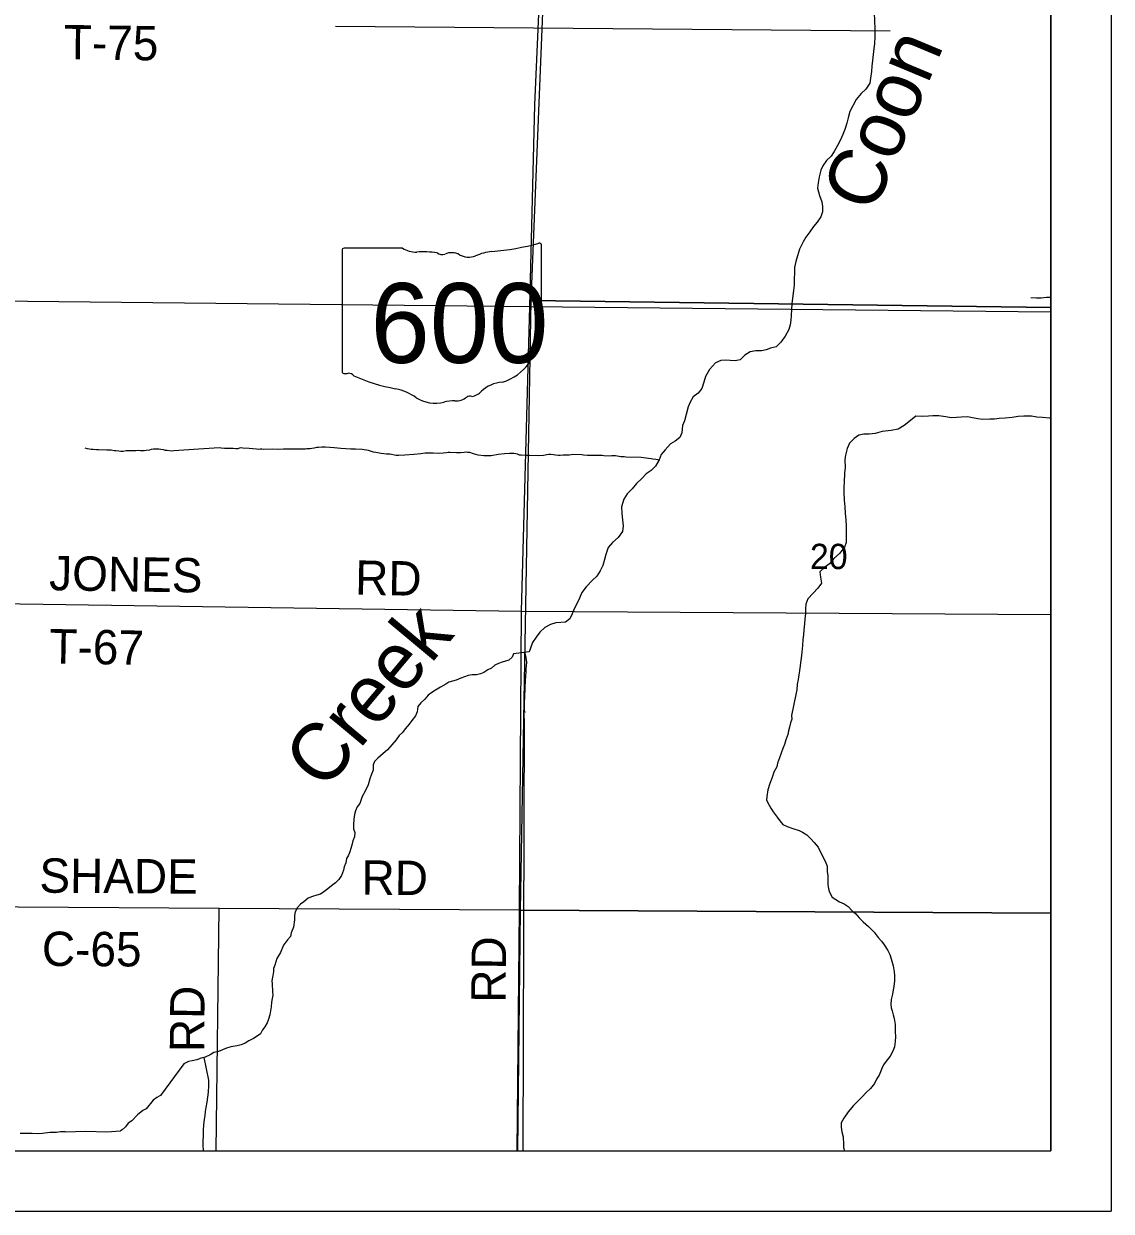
# Model space of a CAD drawing. Extents: x 0 to 34, y 0 to 22.
# Drawn here: x 7.202 to 9, y 14 to 15.963 of the extents above; entities that cross this region are included whole.
import ezdxf

# ---------------------------------------------------------------- set-up
doc = ezdxf.new("R2010")
doc.units = 0
for name, color, linetype in [('Default', 7, 'Continuous'), ('GM_X_County_Road', 7, 'Continuous'), ('GM_X_County_Road_Text', 7, 'Continuous'), ('GM_X_Minor_River', 7, 'Continuous'), ('GM_X_Minor_River_Text', 7, 'Continuous'), ('GM_X_Section_Text', 7, 'Continuous'), ('GM_X_State_Location', 7, 'Continuous'), ('GM_X_State_Route', 7, 'Continuous'), ('GM_X_State_Shield', 7, 'Continuous'), ('GM_X_Township_Road', 7, 'Continuous'), ('GM_X_Township_Road_Text', 7, 'Continuous'), ('SH_Cut_Line', 7, 'Continuous'), ('SH_Data', 7, 'Continuous')]:
    doc.layers.add(name, color=color, linetype=linetype)

msp = doc.modelspace()

# ---------------------------------------------------------------- linework, layer by layer
at = {"layer": 'Default'}
msp.add_lwpolyline([(7.0155, 14.1), (8.9, 14.1), (8.9, 16.9874)], dxfattribs=at)
for points in [[(8.9, 15.4939), (8.9, 16.4924), (8.0805, 16.4987), (8.0402, 15.5054)], [(8.9, 14.4928), (8.9, 15.4939), (8.0402, 15.5054), (8.0226, 14.4979)], [(8.0182, 14.1), (8.9, 14.1), (8.9, 14.4928), (8.0226, 14.4979)]]:
    msp.add_lwpolyline(points, close=True, dxfattribs=at)
at = {"layer": 'GM_X_County_Road'}
msp.add_lwpolyline([(7.0265, 14.5045), (7.5252, 14.501), (8.0219, 14.4983), (8.9, 14.4934)], dxfattribs=at)
at = {"layer": 'GM_X_Minor_River'}
for p, q in [((8.6345, 15.9505), (7.7173, 15.9583)), ((8.0293, 14.8347), (8.0293, 14.8351)), ((8.0295, 14.8146), (8.0271, 14.1))]:
    msp.add_line(p, q, dxfattribs=at)
for points in [[(8.6079, 15.9807), (8.6091, 15.9545), (8.6091, 15.9416), (8.6084, 15.9294), (8.6077, 15.9218)], [(8.6077, 15.9218), (8.6066, 15.9123), (8.6051, 15.9021), (8.6044, 15.8926), (8.6037, 15.8842), (8.6022, 15.8728), (8.6007, 15.8645), (8.5943, 15.855), (8.5864, 15.8477), (8.5784, 15.8374), (8.5679, 15.8176), (8.5653, 15.8073), (8.5626, 15.7986), (8.5593, 15.7883), (8.5563, 15.78), (8.5521, 15.7701), (8.5476, 15.7617), (8.5419, 15.7518), (8.537, 15.7442), (8.5295, 15.7369), (8.5234, 15.7282), (8.5201, 15.7206), (8.5174, 15.7099), (8.5156, 15.6997), (8.5145, 15.6909), (8.5176, 15.6788), (8.5214, 15.6686), (8.5229, 15.661), (8.5226, 15.6519), (8.52, 15.6435), (8.5139, 15.6351), (8.5079, 15.6275), (8.5015, 15.6191), (8.4951, 15.6103), (8.4905, 15.6023), (8.4845, 15.5902), (8.4815, 15.5795), (8.4785, 15.5696), (8.4763, 15.5601), (8.4763, 15.5503), (8.476, 15.5423), (8.4756, 15.5305), (8.4745, 15.5218), (8.4734, 15.5138), (8.472, 15.5001), (8.4712, 15.4906), (8.4709, 15.4808), (8.4705, 15.4728), (8.469, 15.4652), (8.4668, 15.4576), (8.4612, 15.4465), (8.4536, 15.4366), (8.446, 15.429), (8.4369, 15.4267), (8.4294, 15.4236), (8.4218, 15.422), (8.4123, 15.422), (8.4032, 15.4204), (8.3945, 15.4151), (8.3866, 15.4074), (8.3782, 15.4059), (8.3702, 15.4062), (8.3623, 15.4069), (8.3547, 15.4061), (8.346, 15.4023), (8.3361, 15.3916), (8.329, 15.3798), (8.3264, 15.3703), (8.3234, 15.36), (8.3173, 15.352), (8.309, 15.3463), (8.3041, 15.3371), (8.3007, 15.3295), (8.2973, 15.317), (8.2944, 15.3067), (8.2913, 15.2987), (8.2899, 15.2866), (8.2869, 15.279), (8.2793, 15.2728), (8.2714, 15.2682), (8.2627, 15.2587), (8.2562, 15.2507), (8.2529, 15.2423), (8.2468, 15.2313), (8.2393, 15.2244), (8.2309, 15.2191), (8.2238, 15.2111), (8.2151, 15.203), (8.2079, 15.1943), (8.2, 15.1859), (8.1943, 15.1771), (8.1905, 15.1642), (8.191, 15.1532), (8.1921, 15.1426), (8.1929, 15.1327), (8.1918, 15.1236), (8.1851, 15.1137), (8.1756, 15.1056), (8.1684, 15.0969), (8.1643, 15.0855), (8.162, 15.0775)], [(8.9, 15.5101), (8.8931, 15.5103), (8.8844, 15.5095), (8.8764, 15.5095), (8.8673, 15.5098)], [(8.9, 15.311), (8.898, 15.311), (8.8866, 15.3121), (8.8771, 15.3128), (8.868, 15.3143), (8.8555, 15.3142), (8.846, 15.3138), (8.8362, 15.3122), (8.8248, 15.3107), (8.8146, 15.3102), (8.807, 15.3094), (8.799, 15.309), (8.7876, 15.3089), (8.7793, 15.31), (8.7705, 15.3115), (8.7622, 15.313), (8.7519, 15.3125), (8.744, 15.3121), (8.7352, 15.3117), (8.7265, 15.3132), (8.7151, 15.3146), (8.7053, 15.315), (8.6977, 15.3142), (8.6886, 15.3134), (8.6772, 15.314), (8.6681, 15.3068), (8.6579, 15.2988), (8.648, 15.2926), (8.6363, 15.2907), (8.6211, 15.2887), (8.6097, 15.2856), (8.5999, 15.2844), (8.5912, 15.2844), (8.5828, 15.2828), (8.5749, 15.2771), (8.5673, 15.2698), (8.5632, 15.2607), (8.5606, 15.25), (8.5598, 15.2421), (8.5599, 15.2295), (8.5592, 15.22), (8.5585, 15.2052), (8.5581, 15.1973), (8.5581, 15.1881), (8.5586, 15.1752), (8.5597, 15.1646), (8.5602, 15.154), (8.561, 15.1422), (8.5618, 15.1327), (8.5619, 15.1054), (8.5589, 15.0978), (8.5509, 15.0871), (8.5415, 15.0787), (8.5343, 15.0703), (8.5264, 15.0646), (8.5184, 15.057), (8.5192, 15.0479), (8.5208, 15.0384), (8.5151, 15.03), (8.5072, 15.0216), (8.4985, 15.0124), (8.4951, 15.0037), (8.4944, 14.9957), (8.4944, 14.9877), (8.4937, 14.979), (8.4929, 14.971), (8.4918, 14.9612), (8.4911, 14.9528), (8.49, 14.9448), (8.4897, 14.9353), (8.4882, 14.9186), (8.4871, 14.9106), (8.4849, 14.8977), (8.4823, 14.8791), (8.4808, 14.8711), (8.4801, 14.862), (8.4786, 14.8544), (8.4714, 14.8196)], [(7.5955, 15.2595), (7.5928, 15.2595), (7.5901, 15.2592), (7.5871, 15.2596), (7.5807, 15.2601), (7.5746, 15.2609), (7.5644, 15.2614), (7.5607, 15.2619), (7.5553, 15.2604), (7.5527, 15.2601), (7.5485, 15.2605), (7.5421, 15.261), (7.5341, 15.2607), (7.5288, 15.2615), (7.5258, 15.2616), (7.5167, 15.2613), (7.5001, 15.2604), (7.4504, 15.2568), (7.4466, 15.2565), (7.4394, 15.2574), (7.4364, 15.2574), (7.4334, 15.2586), (7.4288, 15.259), (7.4254, 15.2594), (7.4167, 15.2596), (7.4129, 15.2592), (7.4099, 15.2581), (7.4046, 15.2574), (7.4012, 15.2571), (7.3981, 15.2568), (7.3951, 15.2568), (7.3921, 15.2572), (7.3872, 15.2569), (7.3781, 15.257), (7.3743, 15.2567), (7.3716, 15.2567), (7.3667, 15.256), (7.3629, 15.2557), (7.3595, 15.2561), (7.3546, 15.2569), (7.3519, 15.257), (7.3467, 15.2578), (7.3398, 15.2579), (7.3258, 15.2585), (7.3224, 15.2585), (7.3168, 15.259), (7.3134, 15.259), (7.3107, 15.2594), (7.3073, 15.2602), (7.3036, 15.2614)], [(8.254, 15.2407), (8.2506, 15.2423), (8.2472, 15.2427), (8.2423, 15.2432), (8.2393, 15.2436), (8.2348, 15.2444), (8.231, 15.2448), (8.2268, 15.2456), (8.2227, 15.2461), (8.1977, 15.2464), (8.195, 15.2468), (8.1894, 15.2469), (8.1867, 15.2473), (8.1833, 15.2481), (8.1807, 15.2485), (8.1742, 15.2486), (8.1704, 15.2483), (8.1614, 15.2484), (8.1583, 15.2492), (8.1443, 15.2494), (8.1398, 15.249), (8.1341, 15.2491), (8.1273, 15.25), (8.1247, 15.2504), (8.1103, 15.2506), (8.1038, 15.2499), (8.0966, 15.25), (8.094, 15.2496), (8.0887, 15.2493), (8.086, 15.2494), (8.0811, 15.2498), (8.0777, 15.2502), (8.0735, 15.2507), (8.0705, 15.2507), (8.0671, 15.2504), (8.0614, 15.2493), (8.0538, 15.2486), (8.0383, 15.2492), (8.0311, 15.2493), (8.0247, 15.2498), (8.0217, 15.2498), (8.0183, 15.2514), (8.0156, 15.2522), (8.0122, 15.2526), (8.0096, 15.2526), (8.0054, 15.2523), (7.9971, 15.252), (7.9865, 15.2506), (7.9747, 15.2489), (7.963, 15.2487), (7.9535, 15.2499), (7.9456, 15.2519), (7.9396, 15.2539), (7.9362, 15.2543), (7.9335, 15.2547), (7.9301, 15.2544), (7.9244, 15.2537), (7.9176, 15.2538), (7.9066, 15.2543), (7.9036, 15.2544), (7.9009, 15.2537), (7.8956, 15.253), (7.8873, 15.2527), (7.879, 15.2528), (7.8706, 15.2533), (7.8657, 15.253), (7.8589, 15.2519), (7.8471, 15.2509), (7.832, 15.2496), (7.8217, 15.249), (7.8176, 15.249), (7.8074, 15.2515), (7.8017, 15.2515), (7.7972, 15.252), (7.793, 15.2524), (7.7843, 15.254), (7.7805, 15.2548), (7.7771, 15.256), (7.7723, 15.2576), (7.7617, 15.2589), (7.7507, 15.2594), (7.7428, 15.2599), (7.7344, 15.26), (7.7265, 15.2605), (7.7151, 15.2621), (7.708, 15.2622), (7.7004, 15.2627), (7.6951, 15.2628), (7.6894, 15.2625), (7.6868, 15.2625), (7.6822, 15.2614), (7.6784, 15.2607), (7.6757, 15.2604), (7.6704, 15.2601), (7.6678, 15.2597), (7.6523, 15.2595), (7.6314, 15.2598), (7.6231, 15.2592), (7.6136, 15.2597), (7.5981, 15.2591), (7.5955, 15.2595)], [(8.162, 15.0775), (8.1594, 15.0672), (8.1549, 15.0585), (8.1496, 15.0497), (8.1421, 15.0428), (8.1322, 15.0321), (8.1247, 15.0226), (8.1209, 15.0131), (8.1172, 15.0051), (8.1119, 14.996), (8.1089, 14.9872), (8.1051, 14.9792), (8.0976, 14.9739), (8.09, 14.9731), (8.082, 14.9727), (8.0729, 14.9696), (8.0638, 14.965), (8.0551, 14.9573), (8.0491, 14.949), (8.043, 14.9402), (8.04, 14.9307), (8.0376, 14.9245)], [(8.0376, 14.9245), (8.0116, 14.9215), (8.0097, 14.9158), (8.004, 14.9109), (7.9986, 14.9093), (7.9929, 14.9074), (7.9872, 14.9052), (7.9812, 14.9025), (7.9755, 14.8979), (7.9694, 14.8949), (7.9629, 14.8907), (7.9572, 14.8884), (7.9507, 14.8869), (7.9435, 14.8865), (7.9371, 14.8854), (7.931, 14.8835), (7.9249, 14.8812), (7.9169, 14.8778), (7.9112, 14.8763), (7.9051, 14.8744), (7.8998, 14.8713), (7.8911, 14.866), (7.8827, 14.8615), (7.877, 14.8577), (7.8706, 14.8531), (7.8652, 14.8466), (7.8588, 14.8402), (7.8534, 14.8345), (7.8523, 14.8254), (7.85, 14.8189), (7.8436, 14.8109), (7.8394, 14.8052), (7.8325, 14.7976), (7.8284, 14.7912), (7.8226, 14.7862), (7.8181, 14.7794), (7.8109, 14.771), (7.8033, 14.7626), (7.7964, 14.7566), (7.7877, 14.749), (7.782, 14.7436), (7.7801, 14.7376), (7.7797, 14.7292), (7.777, 14.7224), (7.7744, 14.7148), (7.7713, 14.7049), (7.7664, 14.6942), (7.7614, 14.6855), (7.7576, 14.6741), (7.7534, 14.6684), (7.7508, 14.6619), (7.7489, 14.6555), (7.7481, 14.6479), (7.7474, 14.6387), (7.7474, 14.6323), (7.7493, 14.6262), (7.7489, 14.619), (7.7462, 14.6125), (7.7447, 14.6049), (7.7413, 14.5943), (7.739, 14.5886), (7.7359, 14.5832), (7.7344, 14.576), (7.7321, 14.5692), (7.731, 14.5635), (7.7272, 14.5551), (7.723, 14.5483), (7.7177, 14.543), (7.7112, 14.5376), (7.7048, 14.5331), (7.6983, 14.5281), (7.693, 14.524), (7.6865, 14.5224), (7.6793, 14.5205), (7.6724, 14.5175), (7.6652, 14.5114), (7.6595, 14.5076), (7.655, 14.5023), (7.6508, 14.4951), (7.6496, 14.4886), (7.6496, 14.4818), (7.6481, 14.4696), (7.6443, 14.4601), (7.6432, 14.454), (7.6382, 14.4487), (7.6314, 14.4396), (7.6264, 14.4274), (7.6204, 14.4175), (7.6173, 14.4065), (7.615, 14.4012), (7.615, 14.3955), (7.6135, 14.3867), (7.6124, 14.381), (7.6127, 14.3757), (7.6135, 14.3628), (7.6139, 14.3571), (7.6127, 14.3514), (7.6116, 14.3453), (7.6112, 14.3377), (7.6089, 14.3244), (7.607, 14.3176)], [(8.0295, 14.8141), (8.0305, 14.8559), (8.0309, 14.8593), (8.0311, 14.8695), (8.0315, 14.8729), (8.0316, 14.8794), (8.0321, 14.8824), (8.0321, 14.8858), (8.0326, 14.8904), (8.033, 14.8938), (8.033, 14.8972), (8.0335, 14.9006), (8.0336, 14.9082), (8.0332, 14.9109), (8.0325, 14.9154), (8.0304, 14.9237)], [(8.032, 14.8251), (8.0319, 14.8251)], [(8.4714, 14.8196), (8.4721, 14.8135), (8.4698, 14.8074), (8.4679, 14.8002), (8.4664, 14.7941), (8.4652, 14.788), (8.4622, 14.7792), (8.4599, 14.7716), (8.4572, 14.7648), (8.4515, 14.7496), (8.4485, 14.7405), (8.447, 14.7344), (8.4424, 14.7257), (8.4397, 14.7169), (8.4356, 14.707), (8.4321, 14.6964), (8.4306, 14.6854), (8.4302, 14.6793), (8.4344, 14.6713), (8.4374, 14.666), (8.4412, 14.6603), (8.4477, 14.6511), (8.4519, 14.6451), (8.4572, 14.6394), (8.464, 14.6359), (8.4735, 14.6329), (8.4838, 14.6295), (8.4895, 14.6268), (8.4967, 14.6222), (8.5032, 14.6158), (8.5089, 14.6097), (8.5153, 14.6017), (8.5191, 14.5937), (8.5248, 14.5831), (8.5282, 14.5759), (8.5301, 14.5702), (8.5305, 14.5618), (8.5313, 14.5542), (8.5316, 14.5401), (8.5328, 14.5329), (8.5343, 14.5272), (8.5385, 14.5192), (8.5445, 14.5154), (8.5506, 14.5112), (8.5586, 14.5082), (8.5651, 14.5036), (8.5715, 14.4968), (8.5776, 14.4915), (8.5833, 14.485), (8.5901, 14.4785), (8.5989, 14.4709), (8.608, 14.4611), (8.6148, 14.4527), (8.6201, 14.4466), (8.6247, 14.4401), (8.6304, 14.431), (8.6342, 14.4242), (8.6361, 14.4173), (8.6395, 14.4056), (8.641, 14.3957), (8.6414, 14.3896), (8.6414, 14.3808), (8.6406, 14.3713), (8.6395, 14.366), (8.6383, 14.3588), (8.6364, 14.3501), (8.6357, 14.3417), (8.6364, 14.3364), (8.638, 14.3311), (8.6395, 14.3246), (8.641, 14.3185), (8.6425, 14.3086), (8.6429, 14.3018), (8.6429, 14.2965), (8.6436, 14.2889), (8.6429, 14.2805), (8.6414, 14.2718), (8.6391, 14.2645), (8.6345, 14.2565), (8.628, 14.2478), (8.6235, 14.2421), (8.6208, 14.236), (8.6163, 14.225), (8.6121, 14.2182), (8.6086, 14.2113), (8.6018, 14.2026), (8.5946, 14.1961), (8.5881, 14.1893), (8.5798, 14.1809), (8.5737, 14.1748), (8.5653, 14.1642), (8.5577, 14.1536), (8.5535, 14.146), (8.5535, 14.1387), (8.5547, 14.1311), (8.5566, 14.1228), (8.5573, 14.111), (8.5573, 14.1053), (8.5588, 14.1), (8.5588, 14.1)], [(7.607, 14.3176), (7.6047, 14.3115), (7.6009, 14.305), (7.5971, 14.2997), (7.5937, 14.2932), (7.588, 14.2891), (7.5819, 14.2853), (7.5743, 14.2815), (7.5682, 14.2777), (7.5614, 14.275), (7.5549, 14.2735), (7.5443, 14.272), (7.5375, 14.2693), (7.5242, 14.264), (7.5166, 14.2621), (7.5101, 14.2587), (7.5021, 14.2549), (7.4956, 14.253), (7.4881, 14.2503), (7.4808, 14.2488), (7.4744, 14.2473), (7.4671, 14.2435), (7.4284, 14.1914), (7.4223, 14.188), (7.4162, 14.1834), (7.4044, 14.1694), (7.3991, 14.1667), (7.3904, 14.1591), (7.3809, 14.1496), (7.3748, 14.1454), (7.3706, 14.1397), (7.3649, 14.1344), (7.3621, 14.133)], [(7.4997, 14.2542), (7.5074, 14.2169), (7.5074, 14.2077), (7.507, 14.1967), (7.5047, 14.18), (7.5032, 14.1716), (7.5021, 14.1648), (7.5013, 14.1583), (7.5002, 14.1515), (7.4994, 14.1431), (7.499, 14.1332), (7.4986, 14.1237), (7.4983, 14.1176), (7.4983, 14.11), (7.499, 14.1)], [(7.2706, 14.1314), (7.3049, 14.1326), (7.3398, 14.131), (7.3621, 14.133)], [(7.2709, 14.131), (7.2706, 14.1314), (7.2627, 14.131), (7.2562, 14.1299), (7.2452, 14.1299), (7.2334, 14.1283), (7.2243, 14.128), (7.2163, 14.1283), (7.1965, 14.1283)]]:
    msp.add_lwpolyline(points, dxfattribs=at)
at = {"layer": 'GM_X_State_Route'}
msp.add_lwpolyline([(7.0519, 15.5059), (8.039, 15.4956), (8.9, 15.4867)], dxfattribs=at)
at = {"layer": 'GM_X_State_Shield'}
for p, q in [((7.7285, 15.5883), (7.7285, 15.3882)), ((7.8282, 15.5918), (7.7317, 15.5918)), ((8.058, 15.4921), (8.058, 15.5967)), ((8.058, 15.4921), (8.058, 15.4921))]:
    msp.add_line(p, q, dxfattribs=at)
for centre, major_axis, start_param, end_param in [((7.7322, 15.5888), (0.00382, 0), 1.712693, 3.28349), ((7.8512, 15.615), (0.037, 0), 4.042523, 4.731795), ((7.8635, 15.4794), (0.133, 0), 1.404758, 1.657858), ((7.9094, 15.5667), (0.0222, 0), 0.950623, 2.079405), ((7.9852, 15.5307), (0.0703, 0), 1.699011, 2.107814), ((7.9406, 15.8646), (0.3495, 0), 4.814394, 5.042369), ((8.0544, 15.5972), (0.00367, 0), 6.141152, 7.989035), ((7.8937, 15.5898), (0.0107, 0), 3.836095, 5.185415), ((7.938, 15.5984), (0.0267, 0), 4.081561, 5.145723), ((8.0572, 15.4844), (0.00568, 0), 1.883978, 3.671073), ((8.0541, 15.4917), (0.00393, 0), 5.05454, 6.418171), ((8.0211, 15.4711), (0.0341, 0), 5.934695, 6.695948), ((8.0712, 15.4483), (0.0248, 0), 2.387724, 3.262537), ((7.9602, 15.4349), (0.0874, 0), 5.101752, 6.440018), ((7.7323, 15.3878), (0.00385, 0), 3.00124, 4.508301), ((7.7329, 15.4083), (0.0294, 0), 4.665946, 4.897461), ((7.7389, 15.3767), (0.0106, 0), 0.519207, 1.627899), ((7.8727, 15.5565), (0.2524, 0), 4.195997, 4.488961), ((7.9971, 15.332), (0.0479, 0), 1.647645, 2.488434), ((7.7974, 15.2983), (0.079, 0), 0.823519, 1.323587), ((7.9364, 15.3688), (0.0282, 0), 4.937069, 5.64225), ((7.8829, 15.3757), (0.0501, 0), 4.026481, 4.996735), ((7.9118, 15.3065), (0.0412, 0), 1.495662, 1.94098), ((7.9155, 15.3607), (0.0267, 0), 4.691044, 5.507374), ((7.9396, 15.3413), (0.00752, 0), 1.147584, 2.315152)]:
    msp.add_ellipse(centre, major_axis=major_axis, ratio=0.8, start_param=start_param, end_param=end_param, dxfattribs=at)
at = {"layer": 'GM_X_Township_Road'}
for p, q in [((7.0396, 15.006), (8.0249, 14.9917)), ((8.0249, 14.9917), (8.9, 14.9861)), ((7.5201, 14.1), (7.5252, 14.501)), ((8.0178, 14.1), (8.0219, 14.4983))]:
    msp.add_line(p, q, dxfattribs=at)
for points in [[(8.039, 15.4956), (8.0472, 15.8289), (8.0542, 15.9915), (8.07, 16.319), (8.0856, 16.8409), (8.0937, 16.9944)], [(8.0219, 14.4983), (8.0249, 14.9917), (8.039, 15.4956)]]:
    msp.add_lwpolyline(points, dxfattribs=at)
at = {"layer": 'SH_Cut_Line'}
msp.add_lwpolyline([(7.0155, 14.1), (8.9, 14.1), (8.9, 20.9)], dxfattribs=at)
at = {"layer": 'SH_Data'}
for p, q in [((9, 21), (9, 14)), ((8.9, 20.9), (8.9, 14.1)), ((2.1, 14.1), (8.9, 14.1)), ((2, 14), (9, 14))]:
    msp.add_line(p, q, dxfattribs=at)

# ---------------------------------------------------------------- texts
at = {"layer": 'GM_X_County_Road_Text'}
for s, rotation, p in [('SHADE', 359.588, (7.2279, 14.5266)), ('RD', 359.5064, (7.7604, 14.5233)), ('C-65', 359.6571, (7.2321, 14.4055))]:
    msp.add_text(s, height=0.05682, rotation=rotation, dxfattribs=at).set_placement(p)
at = {"layer": 'GM_X_Minor_River_Text'}
for s, rotation, p in [('Coon', 67.3147, (8.6068, 15.6469)), ('Creek', 50.113, (7.6988, 14.6927))]:
    msp.add_text(s, height=0.09476, rotation=rotation, dxfattribs=at).set_placement(p)
at = {"layer": 'GM_X_Section_Text'}
msp.add_text('20', height=0.04186, rotation=0, dxfattribs=at).set_placement((8.5019, 15.0614))
at = {"layer": 'GM_X_State_Location'}
for s, p in [('s', (7.8896, 15.475)), ('r', (7.8895, 15.475))]:
    msp.add_text(s, height=0.000189, dxfattribs=at).set_placement(p)
msp.add_text('600', height=0.000189, rotation=0, dxfattribs=at).set_placement((7.8227, 15.4612))
at = {"layer": 'GM_X_State_Shield'}
msp.add_text('600', height=0.13184, dxfattribs=at).set_placement((7.7754, 15.4023))
at = {"layer": 'GM_X_Township_Road_Text'}
for s, rotation, p in [('T-75', 359.2931, (7.2682, 15.9041)), ('JONES', 359.0838, (7.2439, 15.0266)), ('RD', 359.0128, (7.7497, 15.0191)), ('T-67', 358.9397, (7.2442, 14.9057)), ('RD', 89.5063, (7.9987, 14.3444)), ('RD', 89.5054, (7.5004, 14.2628))]:
    msp.add_text(s, height=0.05682, rotation=rotation, dxfattribs=at).set_placement(p)

doc.saveas('drawing.dxf')
